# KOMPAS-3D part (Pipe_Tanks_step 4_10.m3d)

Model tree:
1. X Axis
2. Y Axis
3. Z Axis  (labels: Bend 90 Dn 150; Pipe Dn 150; Valve Dy 150)
     Òîëùèíà ñòåíêè 1 = 1

Referenced files in C:\Documents and Settings\kashirsky\Мои документы\Camtasia Studio\Pipelines3D\Tanks\: Tanks_step 4.a3d
Referenced files in C:\Program Files\ASCON\KOMPAS-3D V10\Libs\Piping\LOAD\: Piping_C_Pipe_150_1000.m3d
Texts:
  Pipe Dn 150
  Steel ASTM A295
  Three Point Plane
  Plane at Angle
  Line and Point Plane
  Axis through Two Vertices
  Axis of Feature
  Axis of Conical Surface
  Axis through Edge
  Trim by Surface
  Trim by Sketch
  Feature with No History
  Intersection Axis of Two Planes
  Two Line Plane
  Line and Face Plane
  Bend by line
  Hole in sheet body
  Cut in sheet body
  Point in CM
  Linear Dimension from Line to Point
  Surface Finish Symbol
  Geometric Tolerance Symbol
  Leader #1
  Leader #2
  Leader #3
  Shape Deviations and Datum
  Node point number
  Mark of coordination axis
  Node point designation
  Mark/Reference designation with leader
  Mark/reference designation on line
  Mark/Reference designation without leader
  Bend 90 Dn 150
  Valve Dy 150
  Plane of section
